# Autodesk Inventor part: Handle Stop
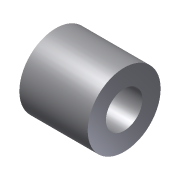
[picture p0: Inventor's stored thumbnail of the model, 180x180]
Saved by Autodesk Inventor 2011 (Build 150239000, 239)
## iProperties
Shininess: 77.0
Length Units: 11269
Angle Units: 11279
Time Units: 11290
Mass Units: 11283
Length Display Precision: 3
Angle Display Precision: 2
Compacted: True
Created: 2002-02
Part Number: Handle Stop
Document SubType Name: Modeling
Designer: ***
Density: 1 g/cm^3
Mass: 2.36248 g
Surface Area: 14.8283 cm^2
Volume: 2.36248 cm^3
Density: 0.0
Volumn: 0.0
Area: 0.0
PropertySet Name: Model Information
Control State: 0
Master: False
Checked Out: False
Author: ***
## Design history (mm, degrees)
sketch "Sketch1"
  geometry: L1 (0, 0)-(0, -2); L2 (0, -2)-(8, -2); L3 (8, -2)-(8, 13); L4 (8, 13)-(4, 13); L5 (4, 13)-(4, 0); L6 (4, 0)-(0, 0)
  constraints: 12 end point, 4 parallel, 1 perpendicular, 1 vertical
  dimensions: "d0" = 16 diameter of L3 L1; "d1" = 8 diameter of L5 L1; "d2" = 2 distance of L1.start L1.end; "d3" = 15 distance of L2.end L3.end
revolve "Revolution1" sketch "Sketch1" stored, may be unused: angle "d4" = 90 deg
body "Solid1"
